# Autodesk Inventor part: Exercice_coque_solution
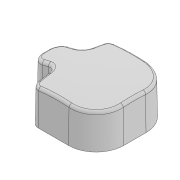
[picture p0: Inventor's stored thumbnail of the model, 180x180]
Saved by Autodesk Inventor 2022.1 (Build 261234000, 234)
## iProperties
Created: 2019-12
Part Number: Exercice_coque_solution
Material: Générique
Document SubType Name: Modeling
Designer: Fabian
Density: 1 g/cm^3
Appearance: Par défaut
Mass: 114.286 g
Surface Area: 775.892 cm^2
Volume: 114.286 cm^3
Author: Fabian
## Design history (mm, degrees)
sketch "Esquisse1"
  geometry: L1 (0, 70)-(0, -66.117); L2 (90, 0)-(-70, 0); L3 (90, 14.325)-(90, 0); L4 (-70, 45)-(-70, 0); L5 (44.578, 70)-(-45, 70); L6 (86.745, 24.649)-(60.961, 61.472); L7 (83, 0)-(83, 5); L8 (65, 23)-(55, 23); L9 (43, 35)-(43, 51); L10 (31, 63)-(-18, 63); L11 (-63, 18)-(-63, 0); L12 (-63, -18)-(-63, 0); L13 (0, -70)-(0, 66.117); L14 (-70, -45)-(-70, 0); L15 (31, -63)-(-18, -63); L16 (44.578, -70)-(-45, -70); L17 (43, -35)-(43, -51); L18 (90, -14.325)-(90, 0); L19 (86.745, -24.649)-(60.961, -61.472); L20 (83, 0)-(83, -5); L21 (65, -23)-(55, -23); C1 r 4 at (-60, 60); C2 r 6 at (55, 35); C3 r 4 at (-60, -60); C4 r 6 at (55, -35); A1 r 15 centre (-60, 60) between (-51, 72) and (-72, 51); A2 r 12 centre (55, 35) between (43, 35) and (55, 23); A3 r 12 centre (31, 51) between (43, 51) and (31, 63); A4 r 18 centre (72, 14.325) between (90, 14.325) and (86.745, 24.649); A5 r 20 centre (44.578, 50) between (60.961, 61.472) and (44.578, 70); A6 r 10 centre (-45, 80) between (-51, 72) and (-45, 70); A7 r 10 centre (-80, 45) between (-70, 45) and (-72, 51); A8 r 18 centre (65, 5) between (83, 5) and (65, 23); A9 r 45 centre (-18, 18) between (-18, 63) and (-63, 18); A10 r 45 centre (-18, -18) between (-63, -18) and (-18, -63); A11 r 12 centre (31, -51) between (31, -63) and (43, -51); A12 r 10 centre (-45, -80) between (-45, -70) and (-51, -72); A13 r 15 centre (-60, -60) between (-72, -51) and (-51, -72); A14 r 10 centre (-80, -45) between (-72, -51) and (-70, -45); A15 r 12 centre (55, -35) between (55, -23) and (43, -35); A16 r 20 centre (44.578, -50) between (44.578, -70) and (60.961, -61.472); A17 r 18 centre (65, -5) between (65, -23) and (83, -5); A18 r 18 centre (72, -14.325) between (86.745, -24.649) and (90, -14.325); 7 further points
  constraints: 44 end point, 40 point on circle, 32 symmetric about line, 22 centre point, 16 tangent, 14 point on line, 5 perpendicular, 4 coincident, 3 vertical, 2 horizontal, 11 other
  dimensions: "d2" = 70 distance between parallel lines of L4 L1; "d3" = 90 distance between parallel lines of L3 L1; "d5" = 30 diameter of A1; "d6" = 140 diameter of L5 L2; "d7" = 20 distance of point (90, 20) L2.start; "d8" = 35 deg angle of L3 L6; "d9" = 120 diameter of A1.centre L2; "d11" = 60 distance from line of A1.centre L1; "d12" = 8 diameter of C1; "d13" = 70 diameter of C2.centre L2; "d14" = 55 distance from line of C2.centre L1; "d15" = 12 diameter of C2; "d16" = 83 distance between parallel lines of L7 L1; "d17" = 63 distance between parallel lines of L11 L1; "d18" = 46 diameter of L8 L2 (derived); "d19" = 126 diameter of L10 L2; "d21" = 12 radius of A2; "d22" = 43 distance between parallel lines of L9 L1 (derived); "d23" = 12 radius of A3 (derived); "d24" = 18 radius of A4 (derived); "d25" = 20 radius of A5; "d26" = 10 radius of A6; "d27" = 10 radius of A7; "d28" = 18 radius of A8; "d29" = 45 radius of A9
extrude "Extrusion1" new body sketch "Esquisse1" distance "d30" = 65; taper "d31" = -1 deg
sketch "Esquisse2"
  geometry: L1 (-81.865, 65)-(61.865, 65); L2 (0, -455)-(0, 65); L3 (18, 65)-(-31, 65) reference; L4 (-55, 65)-(-65, 65) reference; A1 r 260 centre (0, -195) between (0, -455) and (0, 65); 1 further point
  constraints: 4 end point, 2 point on circle, 1 centre point, 1 collinear, 1 point on line, 1 tangent, 1 vertical, 1 vertical alignment
  dimensions: "d32" = 520 diameter of A1
revolve "Révolution1" sketch "Esquisse2" stored, may be unused: angle "d33" = 90 deg
fillet "Congé1" dims "d36" = 5
feature "Coque1" dims "d37" = 3
node "Solide1"
